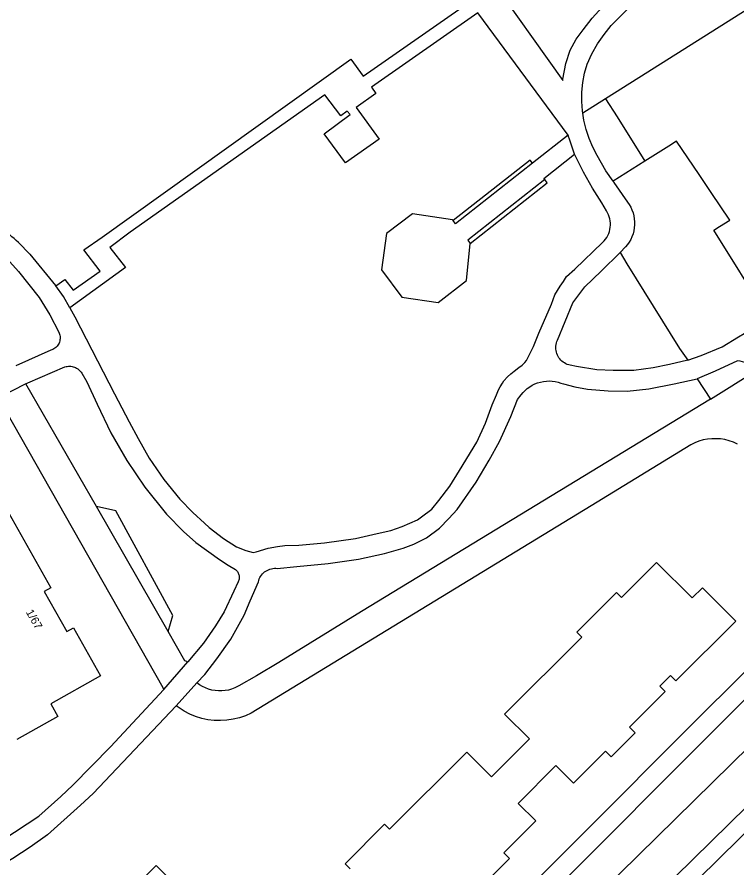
# Model space of a CAD drawing. Extents: x 162791 to 163827, y 385795 to 386523.
# Drawn here: x 163053.2 to 163143.1, y 386115 to 386221.3 of the extents above; entities that cross this region are included whole.
import ezdxf

# ---------------------------------------------------------------- set-up
doc = ezdxf.new("R2010")
doc.units = 0
for name, color, linetype in [('IMGEO_Groenvoorziening', 7, 'Continuous'), ('IMGEO_Pand', 7, 'Continuous'), ('IMGEO_Pand_nummerreeks', 7, 'Continuous'), ('IMGEO_Parkeervlak_open', 7, 'Continuous'), ('IMGEO_Voetpad_open', 7, 'Continuous'), ('IMGEO_Woonerf_gesloten', 7, 'Continuous'), ('IMGEO_Woonerf_open', 7, 'Continuous')]:
    doc.layers.add(name, color=color, linetype=linetype)

msp = doc.modelspace()

# ---------------------------------------------------------------- linework, layer by layer
at = {"layer": 'IMGEO_Groenvoorziening'}
for points in [[(163126.72, 386211.09), (163123.86, 386209.28)], [(163117.59, 386203.03), (163117.29, 386203.43), (163107.67, 386195.86)], [(163109.81, 386193.01), (163119.42, 386200.57), (163119.14, 386200.98)]]:
    msp.add_lwpolyline(points, dxfattribs=at)
at = {"layer": 'IMGEO_Pand'}
for points in [[(163158.27, 386231.02), (163130.88, 386213.71), (163126.72, 386211.09)], [(163162.18, 386208.59), (163167.43, 386211.87), (163165.89, 386214.34), (163168.08, 386215.71), (163176.43, 386202.34), (163146.92, 386183.91), (163140.23, 386194.67), (163140.94, 386195.11), (163142.21, 386195.91), (163139.88, 386199.39), (163138.39, 386201.6), (163135.58, 386205.79), (163134.6, 386205.17), (163131.63, 386203.3)], [(163126.72, 386211.09), (163128.15, 386208.82), (163131.63, 386203.3)], [(163051.02, 386161.31), (163057.44, 386149.97), (163056.61, 386149.5), (163059.44, 386144.5), (163060.27, 386144.97), (163063.65, 386138.99), (163057.43, 386135.47), (163058.31, 386133.91), (163053.2, 386131.02)], [(163094.81, 386114.88), (163094.19, 386115.5), (163099.12, 386120.43), (163099.74, 386119.81), (163109.38, 386129.45), (163112.48, 386126.35), (163117.21, 386131.09), (163114.11, 386134.18), (163123.75, 386143.82), (163123.13, 386144.45), (163128.06, 386149.38), (163128.68, 386148.76), (163133.09, 386153.16)], [(163133.09, 386153.16), (163137.54, 386148.71), (163138.81, 386149.98), (163142.96, 386145.82), (163135.49, 386138.35), (163134.8, 386139.04), (163133.47, 386137.71), (163134.16, 386137.02), (163129.71, 386132.57), (163130.41, 386131.87), (163127.41, 386128.87), (163126.71, 386129.57), (163122.72, 386125.58), (163120.52, 386127.78), (163115.79, 386123.04), (163117.99, 386120.85), (163114, 386116.86), (163114.7, 386116.16), (163111.7, 386113.16)], [(163066.15, 386110.83), (163070.61, 386115.28), (163075.01, 386110.88)]]:
    msp.add_lwpolyline(points, dxfattribs=at)
at = {"layer": 'IMGEO_Parkeervlak_open'}
for points in [[(163072.09, 386144.5), (163063.12, 386160.14)], [(163072.09, 386144.5), (163072.69, 386146.51), (163065.54, 386159.58), (163063.12, 386160.14)]]:
    msp.add_lwpolyline(points, dxfattribs=at)
at = {"layer": 'IMGEO_Voetpad_open'}
for points in [[(163058.05, 386187.72), (163059.18, 386188.5), (163060.22, 386187.16), (163063.6, 386189.54), (163061.56, 386192.21), (163063.86, 386193.8), (163094.9, 386216.01), (163096.44, 386213.92), (163109.74, 386223.18)], [(163110.75, 386221.82), (163097.5, 386212.51), (163098.02, 386211.76), (163095.56, 386210), (163098.45, 386206.04), (163094.22, 386203.06), (163091.55, 386206.71), (163094.83, 386209.1), (163094.46, 386209.55), (163093.67, 386208.95), (163091.66, 386211.58), (163067.36, 386194.4), (163064.81, 386192.51), (163066.76, 386190), (163059.81, 386184.94)], [(163122.04, 386206.53), (163117.59, 386203.03)], [(163122.83, 386204.14), (163122.15, 386206.14), (163122.12, 386206.23), (163122.04, 386206.53)], [(163119.14, 386200.98), (163119.02, 386201.14), (163122.83, 386204.14)], [(163117.59, 386203.03), (163107.98, 386195.47), (163107.67, 386195.86)], [(163131.63, 386203.3), (163127.64, 386200.78)], [(163137, 386178.43), (163138.64, 386178.99), (163141.28, 386180.1), (163143.33, 386181.33), (163144.74, 386182.18), (163147, 386183.52), (163165.46, 386195.06), (163176.71, 386201.87), (163178.31, 386198.47)], [(163119.14, 386200.98), (163109.51, 386193.41), (163109.81, 386193.01)], [(163127.64, 386200.78), (163127.74, 386200.64), (163129.44, 386198.18), (163129.66, 386197.87), (163129.85, 386197.54), (163130.01, 386197.2), (163130.14, 386196.84), (163130.24, 386196.47), (163130.3, 386196.09), (163130.33, 386195.71), (163130.33, 386195.33), (163130.3, 386194.95), (163130.24, 386194.58), (163130.14, 386194.21), (163130.01, 386193.85), (163129.85, 386193.51), (163129.65, 386193.17), (163129.43, 386192.86), (163129.19, 386192.57), (163128.55, 386191.88)], [(163107.67, 386195.86), (163107.59, 386195.96), (163102.62, 386196.71), (163099.37, 386194.23), (163098.72, 386189.72), (163101.28, 386186.28), (163105.8, 386185.63), (163109.35, 386188.38), (163109.81, 386193.01)], [(163128.55, 386191.88), (163129.36, 386190.45), (163135.96, 386179.87), (163137, 386178.43)], [(163059.81, 386184.94), (163059, 386186.38), (163058.05, 386187.72)]]:
    msp.add_lwpolyline(points, dxfattribs=at)
at = {"layer": 'IMGEO_Woonerf_gesloten'}
for points in [[(163109.74, 386223.18), (163108.77, 386224.5), (163112.01, 386226.56), (163121.38, 386213.38), (163121.39, 386213.52), (163121.74, 386215.48), (163122.28, 386217.14), (163123.04, 386218.53), (163123.91, 386219.7), (163125.04, 386221.15), (163126.28, 386222.51), (163127.63, 386223.76), (163129.08, 386224.9), (163130.61, 386225.91), (163168.65, 386243.58)], [(163123.86, 386209.28), (163123.81, 386209.56), (163123.73, 386210.74), (163123.75, 386211.92), (163123.87, 386213.1), (163124.09, 386214.26), (163124.41, 386215.4), (163125.01, 386216.7), (163125.72, 386217.95), (163126.53, 386219.13), (163127.43, 386220.24), (163128.43, 386221.27), (163129.8, 386222.6), (163130.49, 386223.11), (163132.74, 386224.35), (163136.27, 386225.97), (163155.82, 386235.03)], [(163122.04, 386206.53), (163110.75, 386221.82)], [(163127.64, 386200.78), (163126.76, 386202.06), (163125.68, 386204), (163125.12, 386205.04), (163124.65, 386206.12), (163124.27, 386207.24), (163123.99, 386208.39), (163123.86, 386209.28)], [(163059.81, 386184.94), (163060.43, 386183.84), (163065.38, 386174.2), (163067.22, 386170.73), (163068.35, 386168.62), (163069.7, 386166.17), (163071.54, 386163.51), (163073.56, 386161.05), (163075.18, 386159.4), (163076.62, 386158.04), (163077.2, 386157.52), (163079.02, 386156.14), (163080.64, 386155.08), (163081.8, 386154.63), (163082.69, 386154.41), (163083.07, 386154.49), (163084.57, 386154.93), (163085.75, 386155.14), (163086.66, 386155.28), (163088.39, 386155.32), (163091.61, 386155.59), (163095.5, 386156.15), (163098.2, 386156.77), (163099.9, 386157.14), (163101.31, 386157.62), (163103.23, 386158.49), (163103.72, 386158.86), (163105.02, 386159.82), (163105.9, 386160.88), (163107.26, 386162.67), (163108.48, 386164.62), (163110.65, 386168.17), (163111.72, 386170.55), (163112.54, 386172.83), (163113.11, 386174.1), (163113.35, 386174.73), (163113.54, 386175.09), (163113.84, 386175.55), (163114.02, 386175.85), (163114.47, 386176.33), (163114.86, 386176.7), (163115.28, 386177.04), (163115.87, 386177.51), (163116.29, 386177.79), (163116.62, 386178.12), (163116.85, 386178.38), (163117.16, 386179.04), (163117.72, 386180.13), (163118.37, 386181.8), (163119.94, 386185.43), (163120.38, 386186.59), (163121.05, 386187.67), (163121.44, 386188.25), (163121.84, 386188.88), (163122.87, 386189.8), (163126.34, 386193.13), (163126.53, 386193.32), (163126.7, 386193.53), (163126.86, 386193.75), (163126.99, 386193.99), (163127.1, 386194.23), (163127.19, 386194.49), (163127.26, 386194.75), (163127.3, 386195.02), (163127.33, 386195.28), (163127.32, 386195.55), (163127.3, 386195.82), (163127.25, 386196.09), (163127.17, 386196.35), (163127.08, 386196.6), (163126.96, 386196.84), (163126.82, 386197.08), (163126.26, 386198.09), (163125.07, 386199.91), (163123.96, 386201.89), (163122.83, 386204.14)], [(163053.39, 386193.12), (163054.82, 386191.67), (163058.03, 386187.75), (163058.05, 386187.72)], [(163051.56, 386191.53), (163053.38, 386189.5), (163055.96, 386186.24), (163057.31, 386184.1), (163058.43, 386181.93), (163058.49, 386181.8), (163058.53, 386181.66), (163058.57, 386181.53), (163058.59, 386181.39), (163058.6, 386181.25), (163058.6, 386181.1), (163058.58, 386180.96), (163058.56, 386180.82), (163058.52, 386180.69), (163058.46, 386180.56), (163058.4, 386180.43), (163058.33, 386180.31), (163058.24, 386180.19), (163058.15, 386180.09), (163058.05, 386179.99), (163057.93, 386179.9), (163057.82, 386179.83), (163057.69, 386179.76), (163057.56, 386179.7), (163057.43, 386179.66), (163053.05, 386177.72)], [(163137, 386178.43), (163134.71, 386177.86), (163132.65, 386177.47), (163130.25, 386177.15), (163127.65, 386177.12), (163125.63, 386177.23), (163123.1, 386177.61), (163122.29, 386177.79), (163122.11, 386177.84), (163121.93, 386177.9), (163121.75, 386177.98), (163121.58, 386178.07), (163121.42, 386178.18), (163121.27, 386178.3), (163121.13, 386178.43), (163121, 386178.57), (163120.89, 386178.73), (163120.79, 386178.89), (163120.7, 386179.06), (163120.63, 386179.24), (163120.57, 386179.42), (163120.53, 386179.61), (163120.51, 386179.8), (163120.5, 386179.99), (163120.51, 386180.19), (163120.53, 386180.38), (163120.58, 386180.57), (163120.63, 386180.75), (163120.71, 386180.93), (163122.62, 386185.59), (163124.11, 386187.59), (163126.16, 386189.53), (163128.55, 386191.88)], [(163145.58, 386177.19), (163145.4, 386177.37), (163145.17, 386177.57), (163144.92, 386177.74), (163144.66, 386177.9), (163144.39, 386178.04), (163144.1, 386178.15), (163143.8, 386178.23), (163143.51, 386178.29), (163143.2, 386178.32), (163140.39, 386177.04), (163138.14, 386176.08)], [(163054.33, 386175.48), (163054.56, 386175.6), (163059.2, 386177.57), (163059.34, 386177.62), (163059.49, 386177.65), (163059.64, 386177.66), (163059.79, 386177.66), (163059.94, 386177.66), (163060.09, 386177.63), (163060.24, 386177.6), (163060.39, 386177.55), (163060.52, 386177.49), (163060.66, 386177.42), (163060.79, 386177.34), (163060.9, 386177.24), (163061.02, 386177.14), (163061.12, 386177.03), (163061.21, 386176.91), (163061.29, 386176.78), (163061.93, 386175.72), (163063.23, 386172.94), (163064.93, 386169.36), (163066.93, 386165.89), (163069.19, 386162.54), (163071.9, 386159.16), (163074.02, 386157.02), (163075.55, 386155.66), (163078.51, 386153.5), (163079.58, 386152.81), (163080.51, 386152.26), (163080.59, 386152.18), (163080.67, 386152.1), (163080.74, 386152.01), (163080.8, 386151.92), (163080.85, 386151.82), (163080.89, 386151.72), (163080.92, 386151.61), (163080.95, 386151.5), (163080.96, 386151.39), (163080.97, 386151.28), (163080.96, 386151.17), (163080.95, 386151.06), (163080.93, 386150.95), (163080.89, 386150.84), (163080.85, 386150.74), (163080.31, 386149.54), (163079.09, 386146.97), (163077.98, 386145.21), (163076.51, 386143.08), (163074.53, 386140.72)], [(163075.67, 386138.11), (163076.67, 386139.15), (163078.18, 386141.11), (163079.91, 386143.55), (163081.58, 386146.58), (163082.34, 386148.35), (163083.35, 386150.73), (163083.4, 386150.91), (163083.46, 386151.08), (163083.54, 386151.25), (163083.64, 386151.41), (163083.75, 386151.57), (163083.87, 386151.71), (163084, 386151.84), (163084.14, 386151.96), (163084.29, 386152.07), (163084.46, 386152.16), (163084.62, 386152.24), (163084.8, 386152.31), (163084.98, 386152.36), (163085.16, 386152.4), (163085.35, 386152.42), (163085.54, 386152.42), (163085.72, 386152.41), (163088.17, 386152.63), (163092.09, 386153.03), (163095.84, 386153.54), (163099.12, 386154.28), (163101.45, 386154.94), (163102.78, 386155.42), (163104.33, 386156.22), (163105.97, 386157.44), (163107.15, 386158.64), (163108.16, 386159.77), (163110.57, 386163.17), (163112.16, 386165.91), (163113.47, 386168.28), (163114.87, 386171.39), (163115.72, 386173.49), (163116.17, 386174.1), (163116.41, 386174.38), (163116.66, 386174.65), (163116.94, 386174.89), (163117.24, 386175.1), (163117.56, 386175.29), (163117.89, 386175.46), (163118.23, 386175.59), (163118.59, 386175.69), (163118.95, 386175.77), (163119.32, 386175.81), (163119.68, 386175.82), (163120.05, 386175.8), (163120.42, 386175.74), (163120.78, 386175.66), (163121.13, 386175.55), (163121.47, 386175.48), (163122.86, 386175.11), (163124.47, 386174.8), (163127.04, 386174.57), (163129.41, 386174.56), (163132.12, 386174.82), (163135.28, 386175.46), (163138.14, 386176.08)], [(163054.33, 386175.48), (163050.86, 386173.7)], [(163160.51, 386152.14), (163160.79, 386152.33), (163161.79, 386152.23), (163167.2, 386143.82), (163167.25, 386143.63), (163167.29, 386143.43), (163167.3, 386143.23), (163167.31, 386143.03), (163167.29, 386142.83), (163167.26, 386142.64), (163167.21, 386142.44), (163167.15, 386142.25), (163167.07, 386142.07), (163166.97, 386141.89), (163166.86, 386141.73), (163166.74, 386141.57), (163166.6, 386141.42), (163135.7, 386111.04), (163135.22, 386110.58), (163135.12, 386110.69)], [(163078.62, 386073.9), (163090.95, 386086.25), (163109.57, 386104.88), (163137.82, 386133.23), (163155.34, 386150.64)], [(163083.47, 386068.77), (163082.46, 386069.73), (163081.9, 386070.42), (163081.78, 386070.7), (163081.68, 386070.98), (163081.6, 386071.27), (163081.55, 386071.57), (163081.53, 386071.87), (163081.53, 386072.18), (163081.56, 386072.48), (163081.62, 386072.78), (163081.7, 386073.07), (163081.81, 386073.35), (163081.94, 386073.62), (163082.1, 386073.88), (163082.27, 386074.13), (163082.47, 386074.36), (163097.04, 386089.07), (163117.96, 386109.83), (163142.94, 386134.85), (163156.62, 386148.64)], [(163071.55, 386137.29), (163074.53, 386140.72)], [(163073.09, 386135.24), (163075.67, 386138.11)], [(163038.43, 386113.76), (163038.84, 386113.54), (163039.27, 386113.34), (163039.71, 386113.19), (163040.16, 386113.08), (163040.62, 386113.02), (163041.09, 386112.99), (163041.55, 386113.01), (163042.01, 386113.07), (163042.47, 386113.17), (163044.33, 386113.93), (163048.38, 386116.51), (163055.95, 386121.44), (163058.68, 386123.89), (163060.17, 386125.34), (163064.9, 386130.13), (163071.55, 386137.29)], [(163073.09, 386135.24), (163062.74, 386124.27), (163061.15, 386122.84), (163057.04, 386119.12), (163054.85, 386117.59), (163052.69, 386116.17), (163049.48, 386114.23), (163046.01, 386112.24), (163042.01, 386110.03)]]:
    msp.add_lwpolyline(points, dxfattribs=at)
msp.add_arc((163015.76, 386153.24), 54.82, 46.6674, 49.6829, dxfattribs=at)
at = {"layer": 'IMGEO_Woonerf_open'}
for points in [[(163139.83, 386173.53), (163145.58, 386177.19)], [(163138.14, 386176.08), (163139.83, 386173.53)], [(163063.12, 386160.14), (163054.33, 386175.48)], [(163071.55, 386137.29), (163071.46, 386137.47), (163050.86, 386173.7)], [(163139.83, 386173.53), (163096.25, 386147), (163085.91, 386140.64), (163083.12, 386138.98), (163080.93, 386137.74), (163080.4, 386137.47), (163080.01, 386137.32), (163079.61, 386137.21), (163079.2, 386137.14), (163078.78, 386137.1), (163078.36, 386137.1), (163077.95, 386137.14), (163077.54, 386137.21), (163077.14, 386137.32), (163076.74, 386137.47), (163076.37, 386137.65), (163076.01, 386137.86), (163075.67, 386138.11)], [(163143.18, 386167.94), (163142.67, 386168.17), (163142.15, 386168.35), (163141.62, 386168.49), (163141.08, 386168.58), (163140.53, 386168.61), (163139.98, 386168.61), (163139.43, 386168.55), (163138.89, 386168.45), (163138.36, 386168.29), (163137.85, 386168.1), (163137.35, 386167.86), (163124.9, 386160.21), (163082.45, 386134.32), (163081.73, 386133.99), (163080.98, 386133.73), (163080.21, 386133.55), (163079.42, 386133.43), (163078.63, 386133.38), (163077.84, 386133.41), (163077.05, 386133.5), (163076.28, 386133.67), (163075.52, 386133.91), (163074.79, 386134.21), (163074.09, 386134.58), (163073.09, 386135.24)], [(163160.51, 386152.14), (163161.59, 386150.35), (163162.28, 386149.27), (163162.57, 386148.39), (163162.79, 386147.5), (163162.93, 386146.59), (163162.99, 386145.66), (163162.97, 386144.74), (163162.87, 386143.83), (163162.69, 386142.92), (163162.44, 386142.04), (163162.11, 386141.18), (163161.71, 386140.35), (163161.23, 386139.56), (163160.69, 386138.81), (163160.09, 386138.11), (163135.42, 386113.88)], [(163074.53, 386140.72), (163074.17, 386140.87), (163072.09, 386144.5)], [(163123.87, 386109.74), (163156.29, 386141.59)]]:
    msp.add_lwpolyline(points, dxfattribs=at)

# ---------------------------------------------------------------- texts
at = {"layer": 'IMGEO_Pand_nummerreeks'}
msp.add_text('1/67', height=1, rotation=299.7047, dxfattribs=at).set_placement((163054.29, 386146.94))

doc.saveas('drawing.dxf')
